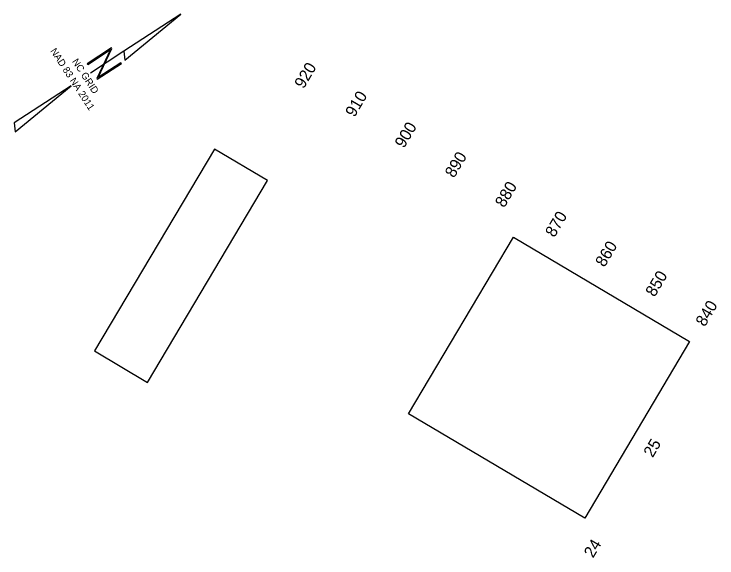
# Model space of a CAD drawing. Extents: x 2138768 to 2143723, y 406633 to 414335.
# Drawn here: x 2143120 to 2143723, y 413868 to 414335 of the extents above; entities that cross this region are included whole.
import ezdxf

# ---------------------------------------------------------------- set-up
doc = ezdxf.new("R2010")
doc.units = 0
for name, color, linetype in [('CTL North Arrow NAD 83 NA 2011 CELL', 7, 'Continuous'), ('Exist Vertical Profile Horizontal Axis Label Major', 7, 'Continuous'), ('Exist Vertical Profile Vertical Axis Label', 7, 'Continuous'), ('Prop Grid Mask', 7, 'Continuous')]:
    doc.layers.add(name, color=color, linetype=linetype)

msp = doc.modelspace()

# ---------------------------------------------------------------- linework, layer by layer
at = {"layer": 'CTL North Arrow NAD 83 NA 2011 CELL'}
msp.add_line((2143190.35, 414287.22), (2143190.35, 414287.22), dxfattribs=at)
for points in [[(2143263.38, 414335.04), (2143214.53, 414303.17), (2143215.41, 414295.54)], [(2143183.05, 414292.46), (2143183.42, 414291.88), (2143202.96, 414304.63), (2143191.3, 414279.81), (2143191.67, 414279.23), (2143212.35, 414292.72), (2143211.97, 414293.3), (2143192.44, 414280.55), (2143204.1, 414305.37), (2143203.72, 414305.95)], [(2143120.3, 414241.7), (2143121.19, 414234.08), (2143169.15, 414273.57)]]:
    msp.add_lwpolyline(points, close=True, dxfattribs=at)
msp.add_lwpolyline([(2143214.53, 414303.17), (2143185.8, 414284.43)], dxfattribs=at)
at = {"layer": 'Prop Grid Mask'}
for points in [[(2143234.77, 414019.06), (2143337.56, 414192.25), (2143292.08, 414219.24), (2143189.29, 414046.06)], [(2143699.56, 414054.01), (2143609.61, 413902.46), (2143458.45, 413992.18), (2143548.4, 414143.73)]]:
    msp.add_lwpolyline(points, close=True, dxfattribs=at)

# ---------------------------------------------------------------- texts
at = {"layer": 'CTL North Arrow NAD 83 NA 2011 CELL'}
for s, p in [('NAD 83 NA 2011', (2143151.16, 414303.35)), ('NC GRID', (2143169.77, 414294.37))]:
    msp.add_text(s, height=6, rotation=303.11885, dxfattribs=at).set_placement(p)
at = {"layer": 'Exist Vertical Profile Horizontal Axis Label Major'}
for s, p in [('25', (2143667.87, 413953.94)), ('24', (2143616.78, 413867.86))]:
    msp.add_text(s, height=10, rotation=59.30926, dxfattribs=at).set_placement(p)
at = {"layer": 'Exist Vertical Profile Vertical Axis Label'}
for s, p in [('920', (2143368.59, 414270.41)), ('910', (2143412.2, 414245.92)), ('900', (2143454.59, 414219.37)), ('890', (2143497.58, 414193.85)), ('880', (2143540.58, 414168.33)), ('870', (2143583.58, 414142.81)), ('860', (2143626.57, 414117.29)), ('850', (2143669.57, 414091.77)), ('840', (2143712.57, 414066.25))]:
    msp.add_text(s, height=10, rotation=59.30926, dxfattribs=at).set_placement(p)

doc.saveas('drawing.dxf')
